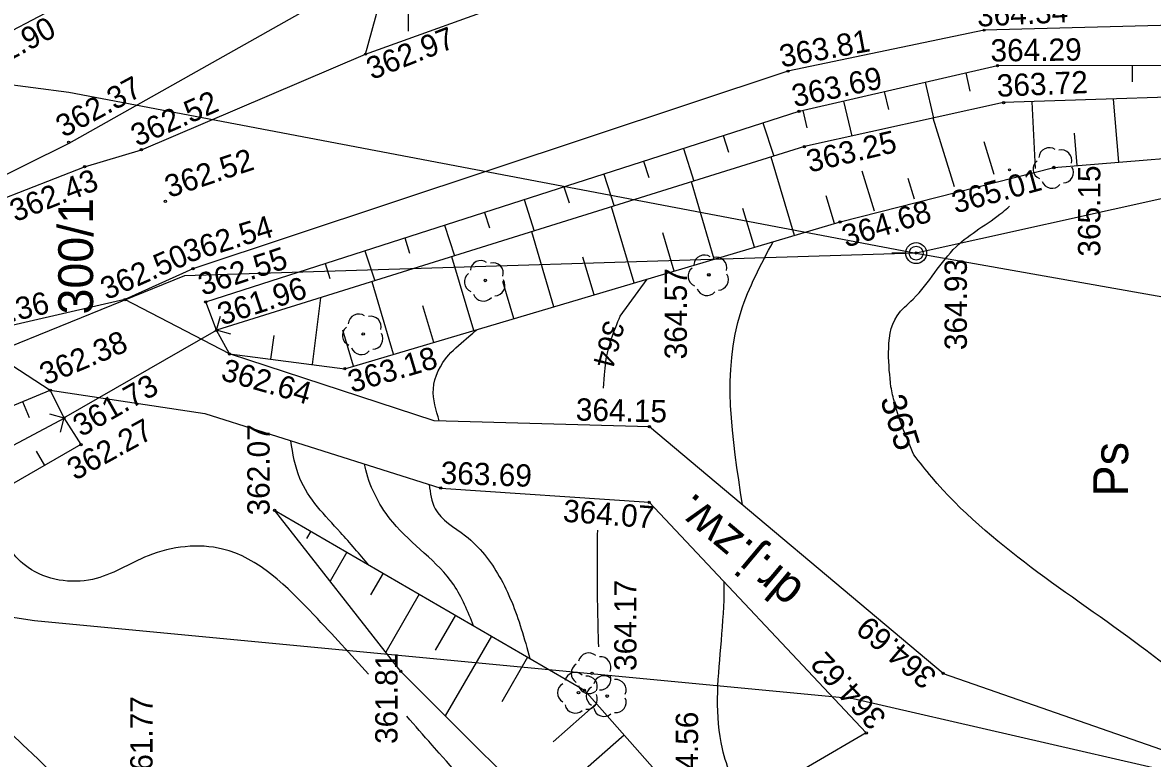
# Model space of a CAD drawing. Extents: x 4635329 to 4651863, y 5356628 to 5367582.
# Drawn here: x 4651223.16 to 4651263.7, y 5356677.75 to 5356704.16 of the extents above; entities that cross this region are included whole.
import ezdxf

# ---------------------------------------------------------------- set-up
doc = ezdxf.new("R2010")
doc.units = 0
for name, color, linetype in [('Level 12', 7, 'Continuous'), ('Level 2', 7, 'Continuous'), ('Level 20', 7, 'Continuous'), ('Level 21', 7, 'Continuous'), ('Level 24', 7, 'Continuous'), ('Level 4', 7, 'Continuous'), ('Level 44', 7, 'Continuous'), ('Level 45', 7, 'Continuous'), ('Level 46', 7, 'Continuous'), ('Level 47', 7, 'Continuous'), ('Level 48', 7, 'Continuous'), ('Level 5', 7, 'Continuous'), ('Level 55', 7, 'Continuous'), ('Level 60', 7, 'Continuous'), ('Level 7', 7, 'Continuous')]:
    doc.layers.add(name, color=color, linetype=linetype)

msp = doc.modelspace()

# ---------------------------------------------------------------- linework, layer by layer
at = {"layer": 'Level 2'}
msp.add_line((4651254.85, 5356695.887), (4651254.35, 5356695.887), dxfattribs=at)
msp.add_circle((4651255.225, 5356695.887), 0.375, dxfattribs=at)
at = {"layer": 'Level 20'}
for p, q in [((4651235.465, 5356703.027), (4651241.485, 5356705.197)), ((4651227.425, 5356699.597), (4651235.465, 5356703.027)), ((4651225.385, 5356698.987), (4651227.425, 5356699.597)), ((4651219.185, 5356696.567), (4651225.385, 5356698.987))]:
    msp.add_line(p, q, dxfattribs=at)
for points in [[(4651235.465, 5356703.027), (4651236.352, 5356706.252), (4651237.175, 5356709.697), (4651240.045, 5356721.267), (4651240.015, 5356727.747), (4651234.475, 5356735.897)], [(4651311.985, 5356685.667), (4651297.855, 5356693.767), (4651287.285, 5356699.227), (4651283.015, 5356700.977), (4651280.145, 5356701.933), (4651275.335, 5356703.187), (4651271.856, 5356703.778), (4651268.065, 5356704.157), (4651257.665, 5356703.887), (4651250.625, 5356702.417), (4651229.275, 5356695.327), (4651226.835, 5356694.217), (4651221.145, 5356692.917), (4651218.085, 5356691.717)], [(4651256.195, 5356680.807), (4651245.655, 5356689.657), (4651237.93, 5356689.868), (4651230.585, 5356692.267), (4651226.835, 5356694.217)], [(4651221.145, 5356692.917), (4651224.155, 5356690.967), (4651229.698, 5356690.126), (4651238.165, 5356687.457), (4651245.645, 5356686.947), (4651253.435, 5356678.667)], [(4651256.195, 5356680.807), (4651265.645, 5356677.517)], [(4651253.435, 5356678.667), (4651247.655, 5356675.297)]]:
    msp.add_lwpolyline(points, dxfattribs=at)
at = {"layer": 'Level 24'}
for p, q in [((4651230.125, 5356693.117), (4651230.264, 5356693.629)), ((4651224.645, 5356689.977), (4651230.125, 5356693.117)), ((4651230.637, 5356692.978), (4651230.125, 5356693.117)), ((4651224.133, 5356690.116), (4651224.645, 5356689.977)), ((4651224.645, 5356689.977), (4651224.506, 5356689.465))]:
    msp.add_line(p, q, dxfattribs=at)
at = {"layer": 'Level 4'}
for p, q in [((4651206.354, 5356704.126), (4651224.825, 5356701.657)), ((4651224.825, 5356701.657), (4651255.225, 5356695.887)), ((4651266.997, 5356698.5), (4651255.225, 5356695.887)), ((4651255.225, 5356695.887), (4651228.971, 5356695.066)), ((4651255.225, 5356695.887), (4651299.165, 5356688.087)), ((4651228.971, 5356695.066), (4651218.267, 5356690.729)), ((4651223.595, 5356682.687), (4651219.808, 5356683.279)), ((4651252.965, 5356679.897), (4651223.595, 5356682.687)), ((4651293.945, 5356670.447), (4651252.965, 5356679.897))]:
    msp.add_line(p, q, dxfattribs=at)
at = {"layer": 'Level 44'}
for centre in [(4651257.665, 5356703.887), (4651235.465, 5356703.027), (4651258.145, 5356702.617), (4651250.625, 5356702.417), (4651251.025, 5356700.977), (4651258.365, 5356701.287), (4651224.815, 5356699.867), (4651251.215, 5356699.707), (4651227.425, 5356699.597), (4651225.385, 5356698.987), (4651260.165, 5356698.957), (4651258.575, 5356698.877), (4651228.285, 5356697.747), (4651252.495, 5356697.007), (4651255.225, 5356695.887), (4651255.225, 5356695.887), (4651255.225, 5356695.887), (4651255.225, 5356695.887), (4651255.225, 5356695.887), (4651255.225, 5356695.887), (4651229.275, 5356695.327), (4651239.765, 5356694.907), (4651247.785, 5356695.107), (4651226.835, 5356694.217), (4651229.735, 5356694.137), (4651230.125, 5356693.117), (4651235.385, 5356692.987), (4651230.585, 5356692.267), (4651234.725, 5356691.737), (4651224.155, 5356690.967), (4651224.645, 5356689.977), (4651245.655, 5356689.657), (4651225.255, 5356689.017), (4651238.165, 5356687.457), (4651245.645, 5356686.947), (4651232.205, 5356686.657), (4651236.735, 5356680.877), (4651256.195, 5356680.807), (4651243.325, 5356680.197), (4651253.435, 5356678.667)]:
    msp.add_circle(centre, 0.04, dxfattribs=at)
at = {"layer": 'Level 46'}
for p, q in [((4651244.609, 5356693.63), (4651245.576, 5356694.955)), ((4651244.002, 5356691.044), (4651244.046, 5356691.52))]:
    msp.add_line(p, q, dxfattribs=at)
for points in [[(4651254.32, 5356691.083), (4651254.236, 5356692.306), (4651254.54, 5356693.64), (4651255.116, 5356694.238), (4651256.663, 5356696.118), (4651258.331, 5356697.361), (4651258.576, 5356697.567)], [(4651248.994, 5356686.853), (4651248.942, 5356693.805), (4651250.095, 5356696.295)], [(4651244.046, 5356691.52), (4651244.089, 5356691.986), (4651244.609, 5356693.63)], [(4651238.113, 5356689.863), (4651237.903, 5356691.016), (4651238.449, 5356692.228), (4651239.177, 5356692.895), (4651239.446, 5356693.137)], [(4651255.142, 5356688.646), (4651254.449, 5356690.518), (4651254.32, 5356691.083)], [(4651235.585, 5356684.693), (4651234.567, 5356685.862), (4651233.111, 5356687.802), (4651232.782, 5356689.154)], [(4651265.764, 5356679.82), (4651263.304, 5356681.756), (4651255.783, 5356687.85), (4651255.142, 5356688.646)], [(4651239.345, 5356682.509), (4651238.631, 5356683.982), (4651236.447, 5356686.226), (4651235.477, 5356688.105), (4651235.427, 5356688.32)], [(4651237.754, 5356687.586), (4651237.964, 5356686.711), (4651239.055, 5356685.741), (4651240.268, 5356684.286), (4651241.057, 5356682.406), (4651241.362, 5356681.337)], [(4651235.574, 5356680.782), (4651233.613, 5356682.904), (4651230.338, 5356685.268), (4651227.669, 5356685.026), (4651225.667, 5356684.177), (4651223.363, 5356684.601), (4651222.271, 5356686.117), (4651222.011, 5356687.156)], [(4651243.786, 5356685.95), (4651243.786, 5356683.255), (4651243.822, 5356681.755)], [(4651228.12, 5356672.269), (4651226.297, 5356674.945), (4651223.325, 5356678.098), (4651221.142, 5356680.341), (4651219.686, 5356682.766), (4651219.019, 5356684.282), (4651218.821, 5356685.129)], [(4651249.021, 5356676.093), (4651248.274, 5356678.101), (4651248.214, 5356681.739), (4651248.335, 5356683.679), (4651248.335, 5356684.088)], [(4651239.172, 5356666.442), (4651239.132, 5356666.654), (4651239.557, 5356670.11), (4651240.709, 5356673.081), (4651237.858, 5356678.235), (4651236.949, 5356679.265)]]:
    msp.add_spline(points, degree=3, dxfattribs=at)
at = {"layer": 'Level 48'}
for p, q in [((4651262.977, 5356702.627), (4651262.978, 5356702.032)), ((4651257.007, 5356702.355), (4651257.156, 5356701.704)), ((4651255.545, 5356702.018), (4651255.842, 5356700.729)), ((4651254.083, 5356701.681), (4651254.23, 5356701.044)), ((4651262.495, 5356699.149), (4651262.309, 5356701.415)), ((4651251.16, 5356701.008), (4651251.304, 5356700.383)), ((4651252.621, 5356701.345), (4651252.912, 5356700.082)), ((4651259.504, 5356698.924), (4651259.383, 5356701.32)), ((4651249.728, 5356700.56), (4651250.113, 5356699.363)), ((4651256.597, 5356698.269), (4651255.84, 5356700.729)), ((4651261, 5356699.026), (4651260.904, 5356700.196)), ((4651248.3, 5356700.102), (4651248.491, 5356699.509)), ((4651258.03, 5356698.709), (4651257.67, 5356699.882)), ((4651246.872, 5356699.643), (4651247.25, 5356698.468)), ((4651250.857, 5356696.521), (4651250.022, 5356699.335)), ((4651245.444, 5356699.184), (4651245.631, 5356698.602)), ((4651244.016, 5356698.725), (4651244.386, 5356697.573)), ((4651253.729, 5356697.387), (4651253.285, 5356698.83)), ((4651255.163, 5356697.828), (4651254.938, 5356698.56)), ((4651242.588, 5356698.266), (4651242.771, 5356697.696)), ((4651247.981, 5356695.668), (4651247.159, 5356698.44)), ((4651241.16, 5356697.808), (4651241.523, 5356696.678)), ((4651252.295, 5356696.948), (4651252.001, 5356697.938)), ((4651239.732, 5356697.349), (4651239.911, 5356696.79)), ((4651245.104, 5356694.815), (4651244.295, 5356697.545)), ((4651249.419, 5356696.095), (4651249.005, 5356697.491)), ((4651238.304, 5356696.89), (4651238.659, 5356695.784)), ((4651242.228, 5356693.962), (4651241.431, 5356696.65)), ((4651246.542, 5356695.242), (4651246.135, 5356696.617)), ((4651236.876, 5356696.431), (4651237.051, 5356695.884)), ((4651235.447, 5356695.972), (4651235.796, 5356694.889)), ((4651239.352, 5356693.109), (4651238.567, 5356695.755)), ((4651243.666, 5356694.389), (4651243.265, 5356695.743)), ((4651234.019, 5356695.513), (4651234.192, 5356694.977)), ((4651236.476, 5356692.256), (4651235.704, 5356694.86)), ((4651240.79, 5356693.536), (4651240.395, 5356694.869)), ((4651233.561, 5356691.886), (4651233.868, 5356694.286)), ((4651237.914, 5356692.683), (4651237.525, 5356693.995)), ((4651232.073, 5356692.077), (4651232.183, 5356692.935)), ((4651235.038, 5356691.83), (4651234.655, 5356693.121)), ((4651223.163, 5356690.557), (4651223.398, 5356689.989)), ((4651223.954, 5356688.271), (4651223.663, 5356688.777)), ((4651233.502, 5356685.904), (4651233.352, 5356685.645)), ((4651234.799, 5356685.15), (4651234.198, 5356684.115)), ((4651236.096, 5356684.397), (4651235.645, 5356683.62)), ((4651237.393, 5356683.643), (4651236.19, 5356681.572)), ((4651238.69, 5356682.89), (4651237.961, 5356681.635)), ((4651239.987, 5356682.136), (4651238.329, 5356679.283)), ((4651241.284, 5356681.383), (4651240.355, 5356679.784)), ((4651243.749, 5356679.718), (4651242.195, 5356678.344)), ((4651244.742, 5356678.594), (4651241.703, 5356675.909))]:
    msp.add_line(p, q, dxfattribs=at)
for points in [[(4651217.225, 5356695.687), (4651221.658, 5356698.264), (4651224.835, 5356699.83), (4651236.075, 5356706.167)], [(4651236.075, 5356706.167), (4651225.165, 5356705.127), (4651221.105, 5356702.987), (4651218.395, 5356700.007)], [(4651229.735, 5356694.137), (4651251.025, 5356700.977), (4651258.145, 5356702.617), (4651267.995, 5356702.637), (4651275.755, 5356701.867), (4651282.555, 5356699.227)], [(4651282.105, 5356698.217), (4651275.815, 5356700.297), (4651267.935, 5356701.597), (4651258.365, 5356701.287), (4651251.215, 5356699.707), (4651230.125, 5356693.117)], [(4651230.585, 5356692.267), (4651234.725, 5356691.737), (4651252.495, 5356697.007), (4651260.165, 5356698.957), (4651267.445, 5356699.557), (4651275.705, 5356698.237), (4651281.905, 5356696.897)], [(4651230.585, 5356692.267), (4651230.125, 5356693.117), (4651229.735, 5356694.137)], [(4651219.005, 5356688.837), (4651224.155, 5356690.967)], [(4651224.155, 5356690.967), (4651224.645, 5356689.977), (4651225.255, 5356689.017)], [(4651218.935, 5356686.927), (4651224.679, 5356689.977)], [(4651225.255, 5356689.017), (4651219.555, 5356685.747)], [(4651247.925, 5356659.557), (4651242.915, 5356674.697), (4651236.735, 5356680.877), (4651232.205, 5356686.657)], [(4651232.205, 5356686.657), (4651243.325, 5356680.197), (4651247.655, 5356675.297), (4651249.645, 5356673.377), (4651252.775, 5356662.007)]]:
    msp.add_lwpolyline(points, dxfattribs=at)
at = {"layer": 'Level 55'}
for centre in [(4651260.165, 5356698.957), (4651239.765, 5356694.907), (4651247.785, 5356695.107), (4651235.385, 5356692.987), (4651243.594, 5356680.808), (4651243.109, 5356680.111), (4651244.139, 5356679.99)]:
    msp.add_circle(centre, 0.045, dxfattribs=at)
for centre, start, end in [((4651260.002, 5356699.295), 55.8648, 175.6487), ((4651260.436, 5356699.216), 343.9073, 103.5587), ((4651259.793, 5356698.906), 127.8655, 247.6473), ((4651260.495, 5356698.78), 271.9043, 31.61), ((4651260.098, 5356698.588), 199.9556, 319.607), ((4651247.622, 5356695.445), 55.8648, 175.6487), ((4651248.056, 5356695.366), 343.9073, 103.5587), ((4651239.602, 5356695.245), 55.8648, 175.6487), ((4651240.036, 5356695.166), 343.9073, 103.5587), ((4651247.413, 5356695.056), 127.8655, 247.6473), ((4651239.393, 5356694.856), 127.8655, 247.6473), ((4651240.095, 5356694.73), 271.9043, 31.61), ((4651248.115, 5356694.93), 271.9043, 31.61), ((4651247.718, 5356694.738), 199.9556, 319.607), ((4651239.698, 5356694.538), 199.9556, 319.607), ((4651235.222, 5356693.325), 55.8648, 175.6487), ((4651235.656, 5356693.246), 343.9073, 103.5587), ((4651235.013, 5356692.936), 127.8655, 247.6473), ((4651235.715, 5356692.81), 271.9043, 31.61), ((4651235.318, 5356692.618), 199.9556, 319.607), ((4651243.478, 5356681.165), 48.1985, 167.8498), ((4651243.219, 5356680.808), 120.1471, 239.8529), ((4651243.897, 5356681.029), 336.1084, 95.8902), ((4651242.992, 5356680.467), 48.1985, 167.8498), ((4651243.412, 5356680.331), 336.1084, 95.8902), ((4651244.023, 5356680.346), 48.1985, 167.8498), ((4651243.897, 5356680.588), 264.1076, 23.8916), ((4651242.734, 5356680.111), 120.1471, 239.8529), ((4651243.478, 5356680.452), 192.1502, 311.8016), ((4651243.764, 5356679.99), 120.1471, 239.8529), ((4651244.443, 5356680.21), 336.1084, 95.8902), ((4651243.412, 5356679.89), 264.1076, 23.8916), ((4651244.443, 5356679.769), 264.1076, 23.8916), ((4651242.992, 5356679.754), 192.1502, 311.8016), ((4651244.023, 5356679.633), 192.1502, 311.8016)]:
    msp.add_arc(centre, 0.375, start, end, dxfattribs=at)
at = {"layer": 'Level 60'}
msp.add_line((4651237.015, 5356703.847), (4651237.015, 5356708.847), dxfattribs=at)
at = {"layer": 'Level 7'}
msp.add_circle((4651255.225, 5356695.887), 0.25, dxfattribs=at)

# ---------------------------------------------------------------- texts
at = {"layer": 'Level 12'}
msp.add_text('Ps', height=1.25, rotation=90, dxfattribs=at).set_placement((4651262.83, 5356687.155))
at = {"layer": 'Level 21'}
msp.add_text('dr.j.zw.', height=1.25, rotation=139.9812, dxfattribs=at).set_placement((4651251.253, 5356683.941))
at = {"layer": 'Level 45'}
for s, rotation, p in [('364.34', 2.9209, (4651257.427, 5356704.012)), ('361.90', 28.0066, (4651221.538, 5356702.167)), ('362.97', 21.4587, (4651235.696, 5356702.094)), ('363.81', 10.4303, (4651250.399, 5356702.546)), ('364.29', 0.6484, (4651257.897, 5356702.761)), ('362.37', 28.3952, (4651224.635, 5356700.016)), ('363.69', 12.1308, (4651250.86, 5356701.121)), ('363.72', 2.3884, (4651258.134, 5356701.495)), ('362.52', 23.7851, (4651227.272, 5356699.696)), ('363.25', 13.3157, (4651251.397, 5356698.774)), ('362.52', 18.6135, (4651228.426, 5356697.862)), ('365.15', 90, (4651261.833, 5356695.76)), ('362.43', 21.4894, (4651222.901, 5356696.993)), ('365.01', 15.2533, (4651256.634, 5356697.302)), ('364.68', 17.246, (4651252.711, 5356696.078)), ('362.54', 17.1321, (4651229.085, 5356695.531)), ('362.50', 23.8537, (4651226.179, 5356694.192)), ('362.55', 18.1824, (4651229.625, 5356694.35)), ('364.57', 90, (4651246.998, 5356692.074)), ('364.93', 90, (4651257.045, 5356692.406)), ('361.96', 18.1543, (4651230.315, 5356693.283)), ('362.36', 13.4045, (4651220.99, 5356692.991)), ('362.38', 22.8028, (4651223.984, 5356691.13)), ('363.18', 16.4293, (4651234.974, 5356690.863)), ('362.64', 343.9851, (4651230.238, 5356691.348)), ('361.73', 29.6637, (4651225.263, 5356689.272)), ('364.15', 358.7625, (4651243.006, 5356689.88)), ('362.27', 28.7971, (4651225.045, 5356687.71)), ('362.07', 90, (4651232.025, 5356686.473)), ('363.69', 357.9606, (4651238.153, 5356687.614)), ('364.07', 355.6562, (4651242.532, 5356686.252)), ('364.17', 90, (4651245.19, 5356680.892)), ('364.69', 139.6034, (4651256.022, 5356680.791)), ('364.62', 133.1705, (4651254.203, 5356679.258)), ('361.81', 90, (4651236.615, 5356678.272)), ('361.77', 90, (4651227.825, 5356676.717)), ('364.56', 90, (4651247.399, 5356676.159))]:
    msp.add_text(s, height=0.8, rotation=rotation, dxfattribs=at).set_placement(p)
at = {"layer": 'Level 47'}
for s, height, rotation, p in [('364', 0.75, 255.2188, (4651244.052, 5356693.517)), ('365', 0.9, 287.5044, (4651253.924, 5356690.647))]:
    msp.add_text(s, height=height, rotation=rotation, dxfattribs=at).set_placement(p)
at = {"layer": 'Level 5'}
msp.add_text('300/1', height=1.25, rotation=90, dxfattribs=at).set_placement((4651225.691, 5356693.684))

doc.saveas('drawing.dxf')
